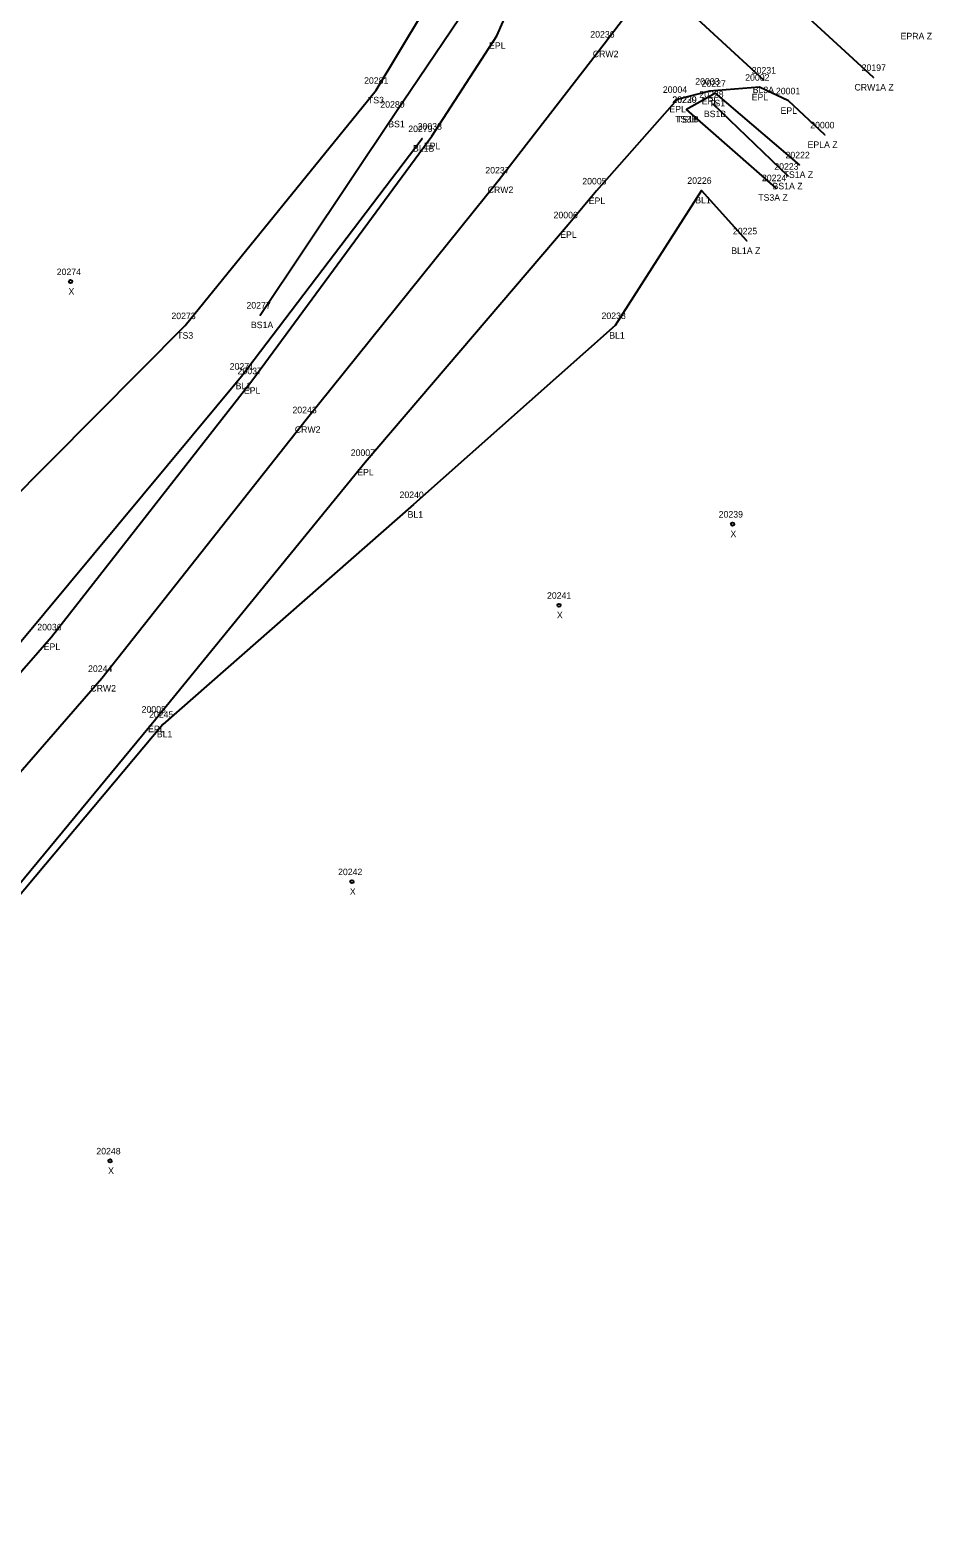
# Model space of a CAD drawing. Extents: x 1813127 to 1814107, y 1178171 to 1179078.
# Drawn here: x 1813940.4 to 1814078.6, y 1178195.8 to 1178426.8 of the extents above; entities that cross this region are included whole.
import ezdxf

# ---------------------------------------------------------------- set-up
doc = ezdxf.new("R2010")
doc.units = 0
for name, color, linetype in [('RD_DTM_BkLn1', 7, 'Continuous'), ('RD_DTM_BkLn2', 7, 'Continuous'), ('RD_EX_Road', 7, 'Continuous'), ('RD_EX_Road_txCode', 7, 'Continuous'), ('RD_SMD_Locator', 7, 'Continuous'), ('RD_SMD_Misc', 7, 'Continuous')]:
    doc.layers.add(name, color=color, linetype=linetype)

msp = doc.modelspace()

# ---------------------------------------------------------------- linework, layer by layer
at = {"layer": 'RD_DTM_BkLn1'}
msp.add_line((1814052.79, 1178419.16), (1814036.46, 1178434.19), dxfattribs=at)
for points in [[(1814069.63, 1178419.56), (1814043.03, 1178443.95), (1814031.76, 1178453.98), (1813994.68, 1178489.07), (1813958.14, 1178523.5), (1813920.87, 1178558.86), (1813884.46, 1178593.47), (1813847.15, 1178628.98), (1813831.28, 1178643.33), (1813810.03, 1178662.5), (1813772.7, 1178693.86)], [(1814043.03, 1178443.95), (1814035.88, 1178434.61), (1814028.35, 1178424.67), (1814012.24, 1178403.85), (1813982.68, 1178367.11), (1813951.35, 1178327.47), (1813918.15, 1178289.3), (1813882.49, 1178251.63), (1813838.5, 1178201.85)], [(1813889.15, 1178276.31), (1813908.67, 1178296.81), (1813972.77, 1178373.79), (1814000.42, 1178410.19)], [(1814050.19, 1178394.52), (1814043.23, 1178402.26), (1814030.04, 1178381.54), (1813999.13, 1178354.11), (1813960.69, 1178320.44), (1813927.58, 1178280.99), (1813899.82, 1178250.55)]]:
    msp.add_lwpolyline(points, dxfattribs=at)
at = {"layer": 'RD_DTM_BkLn2'}
for p, q in [((1814056.53, 1178404.42), (1814045.04, 1178415.48)), ((1814054.64, 1178402.67), (1814040.93, 1178414.66))]:
    msp.add_line(p, q, dxfattribs=at)
for points in [[(1813893.16, 1178338.84), (1813921.32, 1178364.43), (1813929.94, 1178352.15), (1813936.66, 1178353.94), (1813964.13, 1178381.53), (1813993.38, 1178417.59), (1814007.74, 1178441.51), (1813972.38, 1178457.8), (1813931.97, 1178507.78), (1813904.27, 1178536.29), (1813860.78, 1178571.07), (1813835.97, 1178602.37), (1813828.98, 1178599.83), (1813813.84, 1178586.1), (1813811.52, 1178575.86), (1813773.95, 1178566.06)], [(1813975.63, 1178383.15), (1813996.19, 1178413.93), (1814009.95, 1178434.32), (1814012.07, 1178443.24)], [(1814058.25, 1178406.17), (1814045.38, 1178417.13), (1814040.93, 1178414.66)]]:
    msp.add_lwpolyline(points, dxfattribs=at)
at = {"layer": 'RD_EX_Road'}
for points in [[(1813829.87, 1178208.6), (1813830.81, 1178209.56), (1813845.51, 1178227.94), (1813874.69, 1178258.74), (1813910.02, 1178295.38), (1813943.63, 1178333.84), (1813974.31, 1178373.09), (1814001.91, 1178410.56), (1814011.9, 1178425.95), (1814015.58, 1178434.3), (1814016.71, 1178442.08), (1814017.03, 1178447.13), (1814015.19, 1178453.67), (1813986.47, 1178480.85), (1813949.15, 1178515.86), (1813911.94, 1178551.77), (1813875.67, 1178586.1), (1813838.32, 1178620.7), (1813831.51, 1178622), (1813823.35, 1178621.08), (1813815.99, 1178618.51), (1813795.14, 1178605.39)], [(1814062.16, 1178410.76), (1814056.57, 1178415.98), (1814052.15, 1178418.06), (1814044.5, 1178417.46), (1814039.53, 1178416.2), (1814027.18, 1178402.17), (1814022.8, 1178396.98), (1813991.69, 1178360.57), (1813959.64, 1178321.24), (1813927.09, 1178281.88), (1813899.48, 1178251.69), (1813888.9, 1178240.78), (1813846.63, 1178195.79)]]:
    msp.add_lwpolyline(points, dxfattribs=at)
at = {"layer": 'RD_SMD_Locator'}
for centre, radius in [((1814011.9, 1178425.95), 0.001), ((1814028.35, 1178424.67), 0.001), ((1813993.38, 1178417.59), 0.001), ((1814044.5, 1178417.46), 0.001), ((1814052.15, 1178418.06), 0.001), ((1814052.79, 1178419.16), 0.001), ((1814069.63, 1178419.56), 0.001), ((1814039.53, 1178416.2), 0.001), ((1814045.04, 1178415.48), 0.001), ((1814045.38, 1178417.13), 0.001), ((1814056.57, 1178415.98), 0.001), ((1813996.19, 1178413.93), 0.001), ((1814040.93, 1178414.66), 0.001), ((1814040.93, 1178414.66), 0.001), ((1814001.91, 1178410.56), 0.001), ((1814062.16, 1178410.76), 0.001), ((1814000.42, 1178410.19), 0.001), ((1814058.25, 1178406.17), 0.001), ((1814012.24, 1178403.85), 0.001), ((1814056.53, 1178404.42), 0.001), ((1814027.18, 1178402.17), 0.001), ((1814043.23, 1178402.26), 0.001), ((1814054.64, 1178402.67), 0.001), ((1814022.8, 1178396.98), 0.001), ((1814050.19, 1178394.52), 0.001), ((1813946.55, 1178388.28), 0.25), ((1813975.63, 1178383.15), 0.001), ((1813964.13, 1178381.53), 0.001), ((1814030.04, 1178381.54), 0.001), ((1813972.77, 1178373.79), 0.001), ((1813974.31, 1178373.09), 0.001), ((1813982.68, 1178367.11), 0.001), ((1813991.69, 1178360.57), 0.001), ((1813999.13, 1178354.11), 0.001), ((1814048.01, 1178351.12), 0.25), ((1814021.41, 1178338.68), 0.25), ((1813943.63, 1178333.84), 0.001), ((1813951.35, 1178327.47), 0.001), ((1813959.64, 1178321.24), 0.001), ((1813960.69, 1178320.44), 0.001), ((1813989.67, 1178296.33), 0.25), ((1813952.61, 1178253.54), 0.25)]:
    msp.add_circle(centre, radius, dxfattribs=at)

# ---------------------------------------------------------------- texts
at = {"layer": 'RD_EX_Road_txCode'}
for s, p in [('EPL', (1814010.69, 1178423.95)), ('EPRA Z', (1814073.77, 1178425.4)), ('20002', (1814049.95, 1178419.06)), ('20004', (1814037.33, 1178417.2)), ('20003', (1814042.3, 1178418.46)), ('20001', (1814054.66, 1178416.98)), ('EPL', (1814038.33, 1178414.2)), ('EPL', (1814043.29, 1178415.46)), ('EPL', (1814050.94, 1178416.06)), ('EPL', (1814055.37, 1178413.98)), ('20000', (1814059.92, 1178411.76)), ('20038', (1813999.75, 1178411.56)), ('EPL', (1814000.71, 1178408.56)), ('EPLA Z', (1814059.51, 1178408.76)), ('20005', (1814024.98, 1178403.17)), ('EPL', (1814025.97, 1178400.17)), ('20006', (1814020.58, 1178397.98)), ('EPL', (1814021.59, 1178394.98)), ('20037', (1813972.15, 1178374.09)), ('EPL', (1813973.11, 1178371.09)), ('20007', (1813989.49, 1178361.57)), ('EPL', (1813990.48, 1178358.57)), ('20036', (1813941.45, 1178334.84)), ('EPL', (1813942.43, 1178331.84)), ('20008', (1813957.44, 1178322.24)), ('EPL', (1813958.43, 1178319.24))]:
    msp.add_text(s, height=1, dxfattribs=at).set_placement(p)
at = {"layer": 'RD_SMD_Misc'}
for s, p in [('20236', (1814026.21, 1178425.67)), ('CRW2', (1814026.59, 1178422.67)), ('20281', (1813991.54, 1178418.59)), ('20231', (1814050.96, 1178420.16)), ('20197', (1814067.8, 1178420.56)), ('20228', (1814042.92, 1178416.48)), ('20227', (1814043.26, 1178418.13)), ('BL3A', (1814051.1, 1178417.16)), ('CRW1A Z', (1814066.7, 1178417.56)), ('TS3', (1813992.13, 1178415.59)), ('20280', (1813994.03, 1178414.93)), ('20230', (1814038.77, 1178415.66)), ('20229', (1814038.81, 1178415.66)), ('TS1', (1814044.42, 1178415.13)), ('BS1', (1813995.24, 1178411.93)), ('TS3B', (1814039.21, 1178412.66)), ('TS1B', (1814039.5, 1178412.66)), ('BS1B', (1814043.62, 1178413.48)), ('20279', (1813998.31, 1178411.19)), ('BL1B', (1813999.03, 1178408.19)), ('20222', (1814056.13, 1178407.17)), ('20237', (1814010.12, 1178404.85)), ('20223', (1814054.41, 1178405.42)), ('20226', (1814041.08, 1178403.26)), ('20224', (1814052.52, 1178403.67)), ('BS1A Z', (1814054.14, 1178402.42)), ('TS1A Z', (1814055.84, 1178404.17)), ('CRW2', (1814010.48, 1178401.85)), ('BL1', (1814042.3, 1178400.26)), ('TS3A Z', (1814051.95, 1178400.67)), ('20225', (1814048.07, 1178395.52)), ('BL1A Z', (1814047.82, 1178392.52)), ('20274', (1813944.43, 1178389.28)), ('X', (1813946.23, 1178386.28)), ('20277', (1813973.51, 1178384.15)), ('20273', (1813962.01, 1178382.53)), ('20238', (1814027.93, 1178382.54)), ('TS3', (1813962.89, 1178379.53)), ('BS1A', (1813974.19, 1178381.15)), ('BL1', (1814029.12, 1178379.54)), ('20271', (1813970.94, 1178374.79)), ('BL1', (1813971.85, 1178371.79)), ('20243', (1813980.56, 1178368.11)), ('CRW2', (1813980.92, 1178365.11)), ('20240', (1813996.97, 1178355.11)), ('BL1', (1813998.21, 1178352.11)), ('20239', (1814045.89, 1178352.12)), ('X', (1814047.69, 1178349.12)), ('20241', (1814019.57, 1178339.68)), ('X', (1814021.09, 1178336.68)), ('20244', (1813949.23, 1178328.47)), ('CRW2', (1813949.58, 1178325.47)), ('20245', (1813958.58, 1178321.44)), ('BL1', (1813959.77, 1178318.44)), ('20242', (1813987.55, 1178297.33)), ('X', (1813989.35, 1178294.33)), ('20248', (1813950.5, 1178254.54)), ('X', (1813952.3, 1178251.54))]:
    msp.add_text(s, height=1, dxfattribs=at).set_placement(p)

doc.saveas('drawing.dxf')
